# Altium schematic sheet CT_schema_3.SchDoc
size 244 x 211 mm
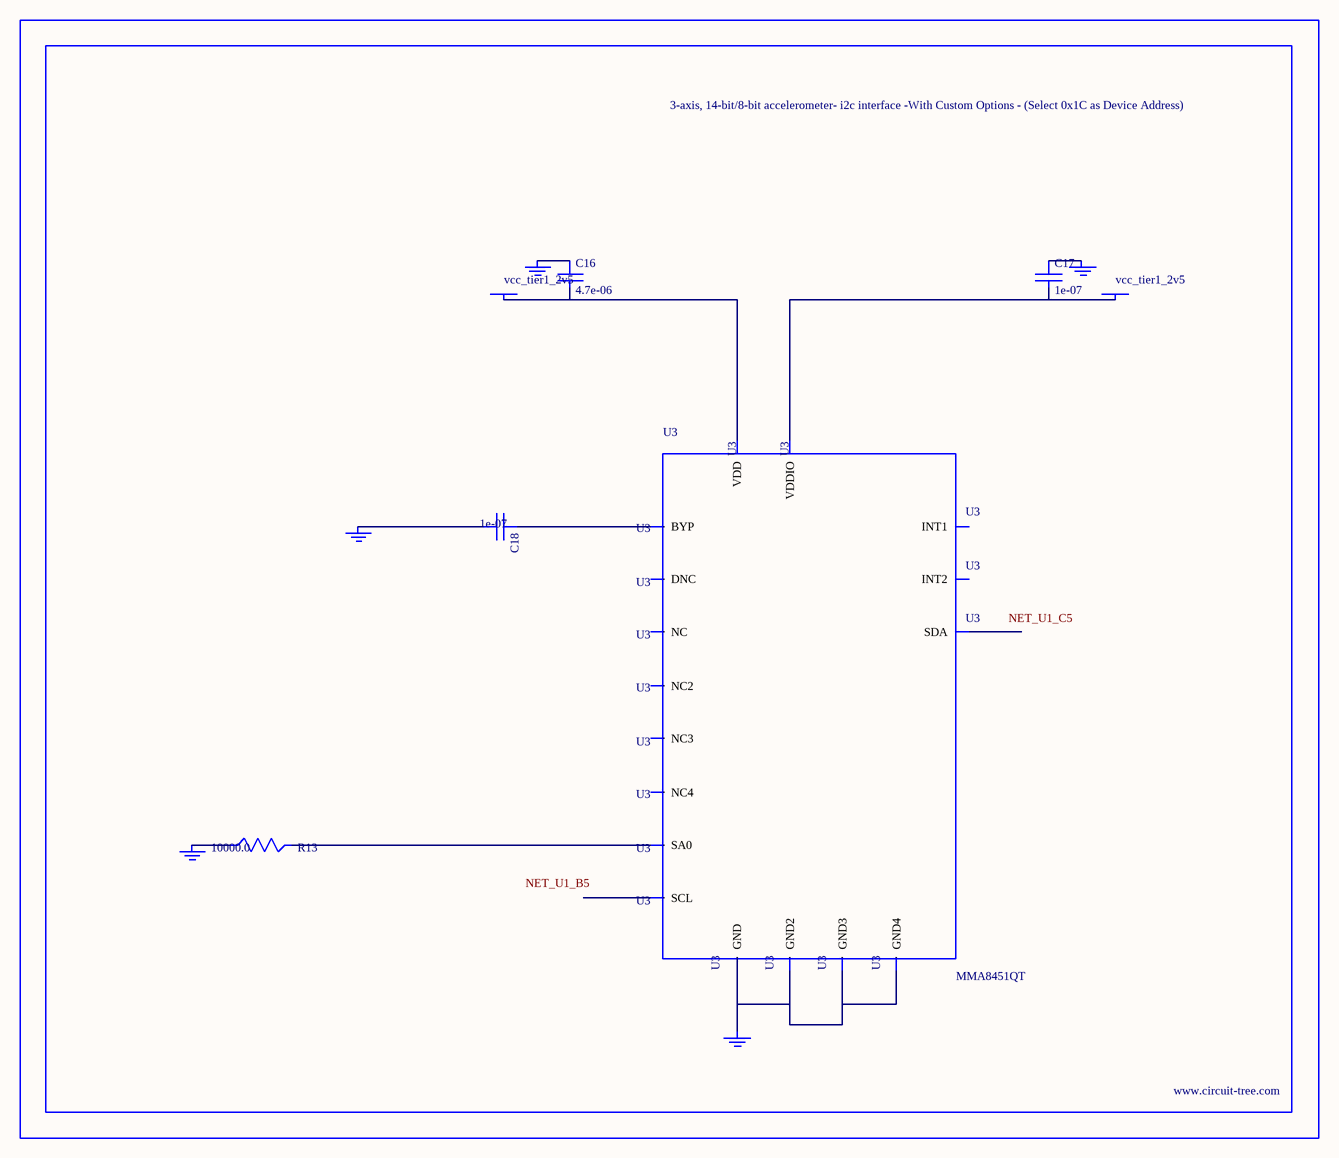
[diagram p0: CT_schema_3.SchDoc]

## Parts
BORDER2  (no value)
C16  4.7e-06  [C0805]
C17  1e-07  [C0402]
C18  1e-07  [C0402]
GND_INSTANCE_2_0  (no value)
GND_INSTANCE_2_1  (no value)
GND_INSTANCE_2_2  (no value)
GND_INSTANCE_2_3  (no value)
GND_INSTANCE_2_4  (no value)
POWER_INSTANCE_2_0  vcc_tier1_2v5
POWER_INSTANCE_2_1  vcc_tier1_2v5
R13  10000.0  [R0603]
U3  MMA8451QT  [QFN-16]

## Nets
NetC16_1: C16.1 GND_INSTANCE_2_3.0(GND)
NetC16_2: C16.2 POWER_INSTANCE_2_1.0(PWR) U3.14(VDD)
NetC17_1: C17.1 GND_INSTANCE_2_0.0(GND)
NetC17_2: C17.2 POWER_INSTANCE_2_0.0(PWR) U3.1(VDDIO)
NetC18_1: C18.1 U3.2(BYP)
NetC18_2: C18.2 GND_INSTANCE_2_1.0(GND)
NetGND_INSTANCE_2_2_0: GND_INSTANCE_2_2.0(GND) R13.1
NetGND_INSTANCE_2_4_0: GND_INSTANCE_2_4.0(GND) U3.5(GND) U3.10(GND2) U3.12(GND3) U3.17(GND4)
NetR13_2: R13.2 U3.7(SA0)

Not connected (* = marked no-connect by the designer): U3 3(DNC) 4(SCL) 6(SDA) 8(NC) 9(INT2) 11(INT1) 13(NC2) 15(NC3) 16(NC4)

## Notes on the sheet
- Labels drawn without touching a wire or pin: NET_U1_B5, NET_U1_C5

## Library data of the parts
BORDER2 = BORDER_PAGE2
C16 = C0805C475K4RACTU
C17 C18 = C0402C104K3RACTU
GND_INSTANCE_2_0-GND_INSTANCE_2_4 = GND
POWER_INSTANCE_2_0 POWER_INSTANCE_2_1 = PWR
R13 = RC0603JR-0710KL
